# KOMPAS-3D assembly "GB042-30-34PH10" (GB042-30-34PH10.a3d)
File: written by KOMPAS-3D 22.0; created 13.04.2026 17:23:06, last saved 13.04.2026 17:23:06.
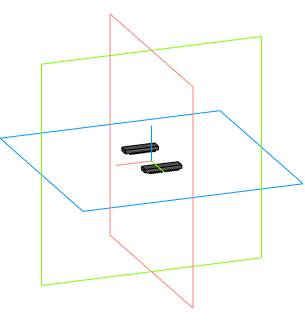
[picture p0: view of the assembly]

Document properties: Автор: Andrey; Полное имя файла: C:\Users\User1\Documents\GB042-30-34PH10.a3d

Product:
- Component [assembly]: ASSEMBLY  | qty 1  | source file: ASSEMBLY_11.a3d
- Part/product: GB042-30-34PH10
    Комментарий: GB042-30-34PH10

Expressions: GB042-30-34PH10
Referenced files in C:\Users\User1\Documents\: ASSEMBLY_11.a3d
